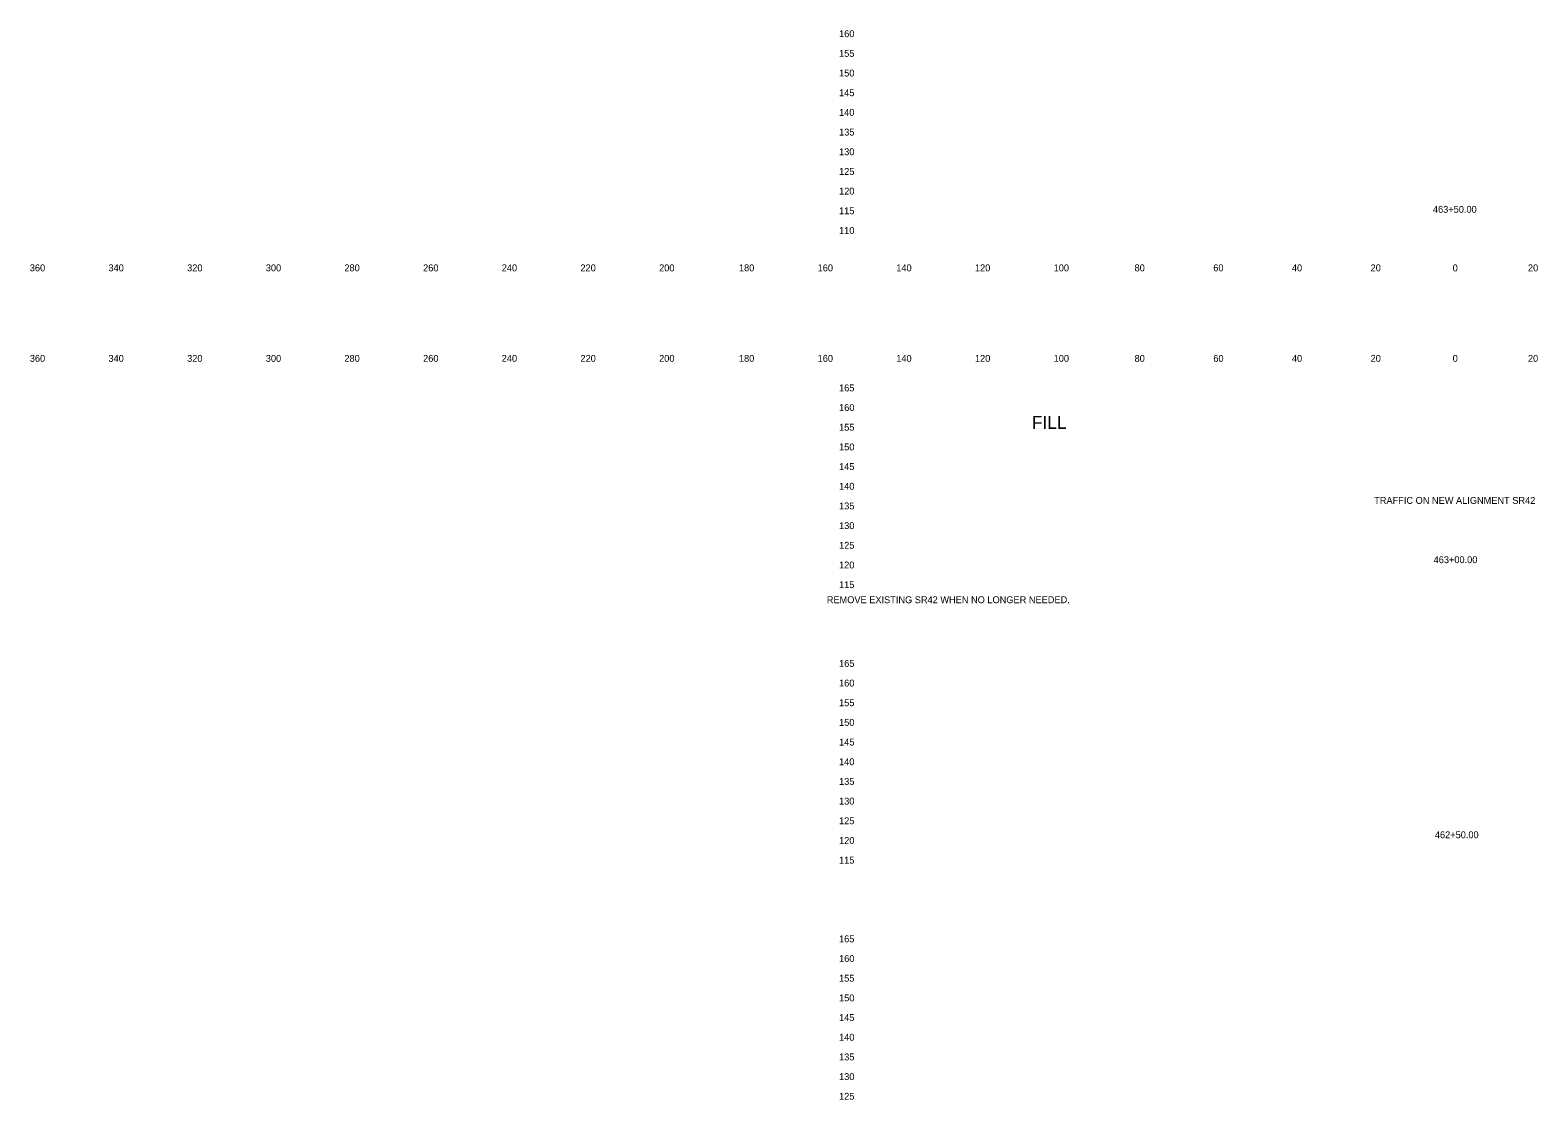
# Model space of a CAD drawing. Extents: x 21281 to 22024, y 6472 to 15208.
# Drawn here: x 21280.5 to 21663.8, y 8104.8 to 8376.6 of the extents above; entities that cross this region are included whole.
import ezdxf

# ---------------------------------------------------------------- set-up
doc = ezdxf.new("R2010")
doc.units = 0
for name, color, linetype in [('XS_SHEET_LABELS_ELEVATION', 7, 'Continuous'), ('XS_SHEET_LABELS_OFFSET', 7, 'Continuous'), ('XS_SHEET_LABELS_STATION', 7, 'Continuous')]:
    doc.layers.add(name, color=color, linetype=linetype)

msp = doc.modelspace()

# ---------------------------------------------------------------- texts
at = {"layer": 'XS_SHEET_LABELS_ELEVATION'}
for s, p in [('  160  ', (21484.84, 8374.84)), ('  155  ', (21484.84, 8369.84)), ('  150  ', (21484.84, 8364.84)), ('  145  ', (21484.84, 8359.84)), ('  140  ', (21484.84, 8354.84)), ('  135  ', (21484.84, 8349.84)), ('  130  ', (21484.84, 8344.84)), ('  125  ', (21484.84, 8339.84)), ('  120  ', (21484.84, 8334.84)), ('  115  ', (21484.84, 8329.84)), ('  110  ', (21484.84, 8324.84)), ('  165  ', (21484.84, 8284.84)), ('  160  ', (21484.84, 8279.84)), ('  155  ', (21484.84, 8274.84)), ('  150  ', (21484.84, 8269.84)), ('  145  ', (21484.84, 8264.84)), ('  140  ', (21484.84, 8259.84)), ('  135  ', (21484.84, 8254.84)), ('  130  ', (21484.84, 8249.84)), ('  125  ', (21484.84, 8244.84)), ('  120  ', (21484.84, 8239.84)), ('  115  ', (21484.84, 8234.84)), ('  165  ', (21484.84, 8214.84)), ('  160  ', (21484.84, 8209.84)), ('  155  ', (21484.84, 8204.84)), ('  150  ', (21484.84, 8199.84)), ('  145  ', (21484.84, 8194.84)), ('  140  ', (21484.84, 8189.84)), ('  135  ', (21484.84, 8184.84)), ('  130  ', (21484.84, 8179.84)), ('  125  ', (21484.84, 8174.84)), ('  120  ', (21484.84, 8169.84)), ('  115  ', (21484.84, 8164.84)), ('  165  ', (21484.84, 8144.84)), ('  160  ', (21484.84, 8139.84)), ('  155  ', (21484.84, 8134.84)), ('  150  ', (21484.84, 8129.84)), ('  145  ', (21484.84, 8124.84)), ('  140  ', (21484.84, 8119.84)), ('  135  ', (21484.84, 8114.84)), ('  130  ', (21484.84, 8109.84)), ('  125  ', (21484.84, 8104.84))]:
    msp.add_text(s, height=1.75, dxfattribs=at).set_placement(p)
at = {"layer": 'XS_SHEET_LABELS_OFFSET'}
for s, height, p in [('  360  ', 1.75, (21279.14, 8315.34)), ('  340  ', 1.75, (21299.13, 8315.34)), ('  320  ', 1.75, (21319.13, 8315.34)), ('  300  ', 1.75, (21339.13, 8315.34)), ('  280  ', 1.75, (21359.1, 8315.34)), ('  260  ', 1.75, (21379.11, 8315.34)), ('  240  ', 1.75, (21399.1, 8315.34)), ('  220  ', 1.75, (21419.1, 8315.34)), ('  200  ', 1.75, (21439.1, 8315.34)), ('  180  ', 1.75, (21459.39, 8315.34)), ('  160  ', 1.75, (21479.4, 8315.34)), ('  140  ', 1.75, (21499.39, 8315.34)), ('  120  ', 1.75, (21519.39, 8315.34)), ('  100  ', 1.75, (21539.39, 8315.34)), ('  80  ', 1.75, (21559.95, 8315.34)), ('  60  ', 1.75, (21579.97, 8315.34)), ('  40  ', 1.75, (21599.95, 8315.34)), ('  20  ', 1.75, (21619.95, 8315.34)), ('  0  ', 1.75, (21640.81, 8315.34)), ('  0  ', 1.75, (21640.81, 8315.34)), ('  20  ', 1.75, (21659.95, 8315.34)), ('  360  ', 1.75, (21279.14, 8292.34)), ('  340  ', 1.75, (21299.13, 8292.34)), ('  320  ', 1.75, (21319.13, 8292.34)), ('  300  ', 1.75, (21339.13, 8292.34)), ('  280  ', 1.75, (21359.1, 8292.34)), ('  260  ', 1.75, (21379.11, 8292.34)), ('  240  ', 1.75, (21399.1, 8292.34)), ('  220  ', 1.75, (21419.1, 8292.34)), ('  200  ', 1.75, (21439.1, 8292.34)), ('  180  ', 1.75, (21459.39, 8292.34)), ('  160  ', 1.75, (21479.4, 8292.34)), ('  140  ', 1.75, (21499.39, 8292.34)), ('  120  ', 1.75, (21519.39, 8292.34)), ('  100  ', 1.75, (21539.39, 8292.34)), ('  80  ', 1.75, (21559.95, 8292.34)), ('  60  ', 1.75, (21579.97, 8292.34)), ('  40  ', 1.75, (21599.95, 8292.34)), ('  20  ', 1.75, (21619.95, 8292.34)), ('  0  ', 1.75, (21640.81, 8292.34)), ('  0  ', 1.75, (21640.81, 8292.34)), ('  20  ', 1.75, (21659.95, 8292.34)), ('FILL', 3.273, (21535.18, 8275.29))]:
    msp.add_text(s, height=height, dxfattribs=at).set_placement(p)
at = {"layer": 'XS_SHEET_LABELS_STATION'}
for s, p in [('  463+50.00  ', (21635.8, 8330.21)), ('TRAFFIC ON NEW ALIGNMENT SR42', (21622.16, 8256.25)), ('  463+00.00  ', (21635.97, 8241.18)), ('REMOVE EXISTING SR42 WHEN NO LONGER NEEDED.', (21483.02, 8231.01)), ('  462+50.00  ', (21636.29, 8171.29))]:
    msp.add_text(s, height=1.75, dxfattribs=at).set_placement(p)

doc.saveas('drawing.dxf')
